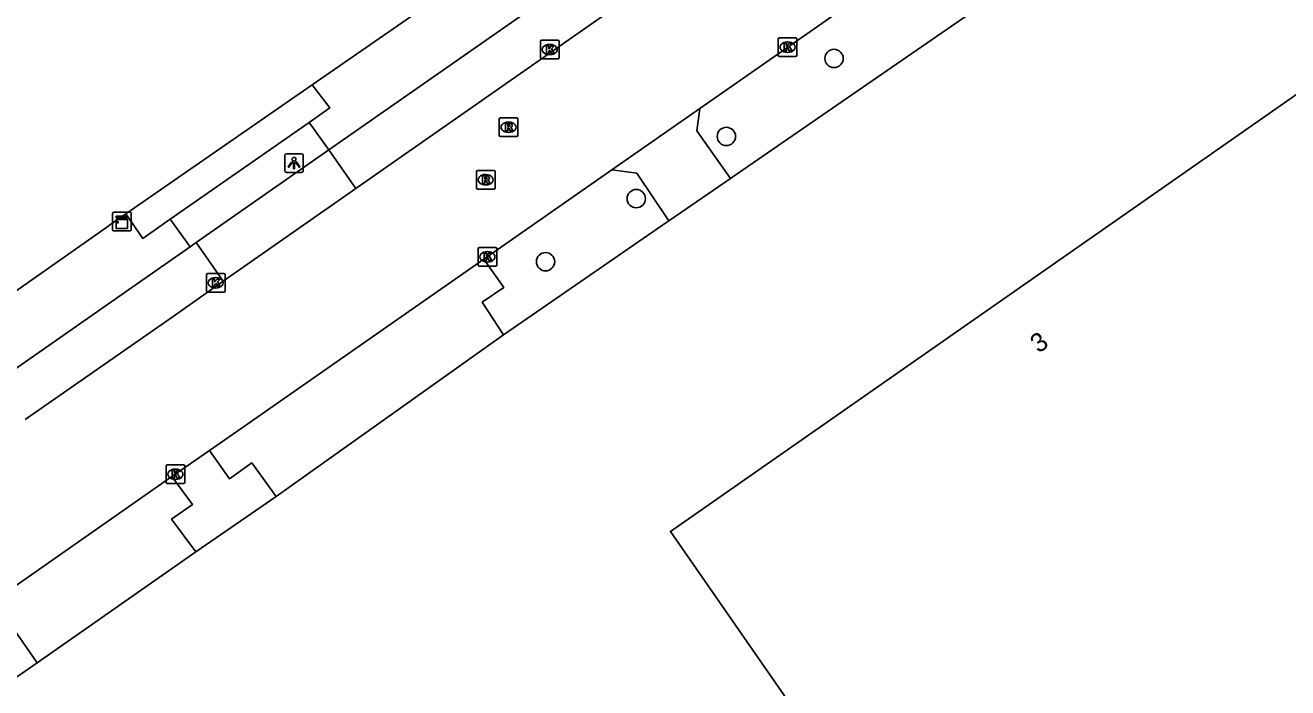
# Model space of a CAD drawing. Extents: x 156651 to 158072, y 387631 to 388990.
# Drawn here: x 157192 to 157259.4, y 388019.3 to 388054.7 of the extents above; entities that cross this region are included whole.
import ezdxf

# ---------------------------------------------------------------- set-up
doc = ezdxf.new("R2010")
doc.units = 0
for name, color, linetype in [('IMGEO_Berm_groen', 7, 'Continuous'), ('IMGEO_Boom', 7, 'Continuous'), ('IMGEO_Groenvoorziening', 7, 'Continuous'), ('IMGEO_Hek', 7, 'Continuous'), ('IMGEO_Kast', 7, 'Continuous'), ('IMGEO_Kolk', 7, 'Continuous'), ('IMGEO_Lichtpunt', 7, 'Continuous'), ('IMGEO_Pand', 7, 'Continuous'), ('IMGEO_Pand_nummerreeks', 7, 'Continuous'), ('IMGEO_Parkeervlak_open', 7, 'Continuous'), ('IMGEO_Rijbaan_lokaal_gesloten', 7, 'Continuous'), ('IMGEO_Rioolput', 7, 'Continuous'), ('IMGEO_Voetpad_open', 7, 'Continuous')]:
    doc.layers.add(name, color=color, linetype=linetype)

msp = doc.modelspace()

# ---------------------------------------------------------------- linework, layer by layer
at = {"layer": 'IMGEO_Berm_groen'}
for points in [[(157229.656, 388046.52), (157229.78, 388046.605), (157243.07, 388055.771)], [(157217.532, 388038.158), (157226.257, 388044.175), (157226.369, 388044.252)], [(157201.094, 388026.55), (157205.385, 388029.517)], [(157173.094, 388007.069), (157192.622, 388020.62)]]:
    msp.add_lwpolyline(points, dxfattribs=at)
at = {"layer": 'IMGEO_Boom'}
for centre in [(157235.188, 388052.93), (157229.437, 388048.762), (157224.623, 388045.438), (157219.777, 388042.063)]:
    msp.add_circle(centre, 0.489, dxfattribs=at)
at = {"layer": 'IMGEO_Groenvoorziening'}
msp.add_lwpolyline([(157207.322, 388051.52), (157197.352, 388044.618)], dxfattribs=at)
at = {"layer": 'IMGEO_Hek'}
for points in [[(157207.322, 388051.52), (157218.564, 388059.333)], [(157197.352, 388044.618), (157207.322, 388051.52)], [(157196.491, 388044.015), (157197.352, 388044.618)], [(157190.094, 388039.531), (157196.391, 388043.945)], [(157196.391, 388043.945), (157196.491, 388044.015)]]:
    msp.add_lwpolyline(points, dxfattribs=at)
at = {"layer": 'IMGEO_Kast'}
for p, q in [((157196.646, 388043.786), (157196.646, 388044.627)), ((157196.646, 388044.627), (157196.646, 388043.786)), ((157196.721, 388044.711), (157197.562, 388044.711)), ((157197.562, 388044.711), (157196.721, 388044.711)), ((157197.646, 388044.636), (157197.646, 388043.795)), ((157197.646, 388043.795), (157197.646, 388044.636)), ((157197.571, 388043.711), (157196.73, 388043.711)), ((157196.73, 388043.711), (157197.571, 388043.711))]:
    msp.add_line(p, q, dxfattribs=at)
for points in [[(157196.841, 388044.501), (157197.441, 388044.501), (157197.441, 388044.416), (157196.841, 388044.416), (157196.841, 388044.501)], [(157196.841, 388044.326), (157197.441, 388044.326), (157197.441, 388043.837), (157196.841, 388043.837), (157196.841, 388044.326)]]:
    msp.add_lwpolyline(points, dxfattribs=at)
msp.add_circle((157196.925, 388044.175), 0.0377, dxfattribs=at)
for centre, start, end in [((157196.724, 388044.633), 92.4484, 184.28452), ((157196.724, 388044.633), 92.4484, 184.28452), ((157197.568, 388044.633), 2.4484, 94.28452), ((157197.568, 388044.633), 2.4484, 94.28452), ((157196.724, 388043.789), 182.4484, 274.28452), ((157196.724, 388043.789), 182.4484, 274.28452), ((157197.568, 388043.789), 272.4484, 4.28452), ((157197.568, 388043.789), 272.4484, 4.28452)]:
    msp.add_arc(centre, 0.0779, start, end, dxfattribs=at)
at = {"layer": 'IMGEO_Kolk'}
for p, q in [((157219.503, 388052.979), (157219.503, 388053.831)), ((157219.578, 388053.905), (157220.43, 388053.905)), ((157220.504, 388053.831), (157220.504, 388052.979)), ((157232.204, 388053.109), (157232.204, 388053.961)), ((157232.279, 388054.035), (157233.131, 388054.035)), ((157232.692, 388053.815), (157232.717, 388053.815)), ((157233.205, 388053.961), (157233.205, 388053.109)), ((157220.014, 388053.125), (157219.989, 388053.125)), ((157219.991, 388053.685), (157220.016, 388053.685)), ((157232.715, 388053.255), (157232.69, 388053.255)), ((157220.43, 388052.905), (157219.578, 388052.905)), ((157233.131, 388053.035), (157232.279, 388053.035)), ((157216.173, 388041.901), (157216.173, 388042.753)), ((157216.248, 388042.827), (157217.1, 388042.827)), ((157216.661, 388042.607), (157216.686, 388042.607)), ((157217.174, 388042.753), (157217.174, 388041.901)), ((157217.1, 388041.827), (157216.248, 388041.827)), ((157216.684, 388042.047), (157216.659, 388042.047)), ((157201.661, 388040.513), (157201.661, 388041.365)), ((157201.736, 388041.439), (157202.588, 388041.439)), ((157202.149, 388041.219), (157202.174, 388041.219)), ((157202.662, 388041.365), (157202.662, 388040.513)), ((157202.588, 388040.439), (157201.736, 388040.439)), ((157202.172, 388040.659), (157202.147, 388040.659)), ((157199.509, 388030.275), (157199.509, 388031.127)), ((157199.584, 388031.201), (157200.436, 388031.201)), ((157199.997, 388030.981), (157200.022, 388030.981)), ((157200.51, 388031.127), (157200.51, 388030.275)), ((157200.436, 388030.201), (157199.584, 388030.201)), ((157200.02, 388030.421), (157199.995, 388030.421))]:
    msp.add_line(p, q, dxfattribs=at)
for points in [[(157219.503, 388052.979), (157219.503, 388053.831)], [(157219.578, 388053.905), (157220.43, 388053.905)], [(157220.504, 388053.831), (157220.504, 388052.979)], [(157232.204, 388053.109), (157232.204, 388053.961)], [(157232.279, 388054.035), (157233.131, 388054.035)], [(157232.525, 388053.735), (157232.648, 388053.735), (157232.648, 388053.584), (157232.778, 388053.735), (157232.942, 388053.735), (157232.796, 388053.584), (157232.949, 388053.335), (157232.797, 388053.335), (157232.712, 388053.499), (157232.648, 388053.432), (157232.648, 388053.335), (157232.525, 388053.335), (157232.525, 388053.735)], [(157233.205, 388053.961), (157233.205, 388053.109)], [(157219.824, 388053.605), (157219.947, 388053.605), (157219.947, 388053.454), (157220.077, 388053.605), (157220.241, 388053.605), (157220.095, 388053.454), (157220.248, 388053.205), (157220.096, 388053.205), (157220.011, 388053.369), (157219.947, 388053.302), (157219.947, 388053.205), (157219.824, 388053.205), (157219.824, 388053.605)], [(157220.43, 388052.905), (157219.578, 388052.905)], [(157233.131, 388053.035), (157232.279, 388053.035)], [(157216.173, 388041.901), (157216.173, 388042.753)], [(157216.248, 388042.827), (157217.1, 388042.827)], [(157216.494, 388042.527), (157216.617, 388042.527), (157216.617, 388042.376), (157216.747, 388042.527), (157216.911, 388042.527), (157216.765, 388042.376), (157216.918, 388042.127), (157216.766, 388042.127), (157216.681, 388042.291), (157216.617, 388042.224), (157216.617, 388042.127), (157216.494, 388042.127), (157216.494, 388042.527)], [(157217.174, 388042.753), (157217.174, 388041.901)], [(157217.1, 388041.827), (157216.248, 388041.827)], [(157201.661, 388040.513), (157201.661, 388041.365)], [(157201.736, 388041.439), (157202.588, 388041.439)], [(157201.982, 388041.139), (157202.105, 388041.139), (157202.105, 388040.988), (157202.235, 388041.139), (157202.399, 388041.139), (157202.253, 388040.988), (157202.406, 388040.739), (157202.254, 388040.739), (157202.169, 388040.903), (157202.105, 388040.836), (157202.105, 388040.739), (157201.982, 388040.739), (157201.982, 388041.139)], [(157202.662, 388041.365), (157202.662, 388040.513)], [(157202.588, 388040.439), (157201.736, 388040.439)], [(157199.509, 388030.275), (157199.509, 388031.127)], [(157199.584, 388031.201), (157200.436, 388031.201)], [(157199.83, 388030.901), (157199.953, 388030.901), (157199.953, 388030.75), (157200.083, 388030.901), (157200.247, 388030.901), (157200.101, 388030.75), (157200.254, 388030.501), (157200.102, 388030.501), (157200.017, 388030.665), (157199.953, 388030.598), (157199.953, 388030.501), (157199.83, 388030.501), (157199.83, 388030.901)], [(157200.51, 388031.127), (157200.51, 388030.275)], [(157200.436, 388030.201), (157199.584, 388030.201)]]:
    msp.add_lwpolyline(points, dxfattribs=at)
for centre, start, end in [((157219.58, 388053.829), 91.55205, 178.44795), ((157219.58, 388053.829), 91.55205, 178.44795), ((157220.428, 388053.829), 1.55205, 88.44795), ((157220.428, 388053.829), 1.55205, 88.44795), ((157232.281, 388053.959), 91.55205, 178.44795), ((157232.281, 388053.959), 91.55205, 178.44795), ((157233.129, 388053.959), 1.55205, 88.44795), ((157233.129, 388053.959), 1.55205, 88.44795), ((157232.281, 388053.111), 181.55205, 268.44795), ((157232.281, 388053.111), 181.55205, 268.44795), ((157233.129, 388053.111), 271.55205, 358.44795), ((157233.129, 388053.111), 271.55205, 358.44795), ((157219.58, 388052.981), 181.55205, 268.44795), ((157219.58, 388052.981), 181.55205, 268.44795), ((157220.428, 388052.981), 271.55205, 358.44795), ((157220.428, 388052.981), 271.55205, 358.44795), ((157216.25, 388042.751), 91.55205, 178.44795), ((157216.25, 388042.751), 91.55205, 178.44795), ((157217.098, 388042.751), 1.55205, 88.44795), ((157217.098, 388042.751), 1.55205, 88.44795), ((157216.25, 388041.903), 181.55205, 268.44795), ((157216.25, 388041.903), 181.55205, 268.44795), ((157217.098, 388041.903), 271.55205, 358.44795), ((157217.098, 388041.903), 271.55205, 358.44795), ((157201.738, 388041.363), 91.55205, 178.44795), ((157201.738, 388041.363), 91.55205, 178.44795), ((157202.586, 388041.363), 1.55205, 88.44795), ((157202.586, 388041.363), 1.55205, 88.44795), ((157201.738, 388040.515), 181.55205, 268.44795), ((157201.738, 388040.515), 181.55205, 268.44795), ((157202.586, 388040.515), 271.55205, 358.44795), ((157202.586, 388040.515), 271.55205, 358.44795), ((157199.586, 388031.125), 91.55205, 178.44795), ((157199.586, 388031.125), 91.55205, 178.44795), ((157200.434, 388031.125), 1.55205, 88.44795), ((157200.434, 388031.125), 1.55205, 88.44795), ((157199.586, 388030.277), 181.55205, 268.44795), ((157199.586, 388030.277), 181.55205, 268.44795), ((157200.434, 388030.277), 271.55205, 358.44795), ((157200.434, 388030.277), 271.55205, 358.44795)]:
    msp.add_arc(centre, 0.0765, start, end, dxfattribs=at)
for centre, major_axis, ratio, start_param, end_param in [((157232.691, 388053.535), (-0.387, 0.002), 0.722429, 4.712389, 7.853982), ((157232.716, 388053.535), (-0.39, 0.002), 0.717154, 1.570796, 4.712389), ((157219.99, 388053.405), (-0.387, 0.002), 0.722429, 4.712389, 7.853982), ((157220.015, 388053.405), (-0.39, 0.002), 0.717154, 1.570796, 4.712389), ((157216.66, 388042.327), (-0.387, 0.002), 0.722429, 4.712389, 7.853982), ((157216.685, 388042.327), (-0.39, 0.002), 0.717154, 1.570796, 4.712389), ((157202.148, 388040.939), (-0.387, 0.002), 0.722429, 4.712389, 7.853982), ((157202.173, 388040.939), (-0.39, 0.002), 0.717154, 1.570796, 4.712389), ((157199.996, 388030.701), (-0.387, 0.002), 0.722429, 4.712389, 7.853982), ((157200.021, 388030.701), (-0.39, 0.002), 0.717154, 1.570796, 4.712389)]:
    msp.add_ellipse(centre, major_axis=major_axis, ratio=ratio, start_param=start_param, end_param=end_param, dxfattribs=at)
at = {"layer": 'IMGEO_Lichtpunt'}
for p, q in [((157205.845, 388047.743), (157205.845, 388046.936)), ((157205.845, 388047.743), (157205.845, 388046.936)), ((157206.747, 388047.838), (157205.939, 388047.838)), ((157206.747, 388047.838), (157205.939, 388047.838)), ((157206.841, 388046.936), (157206.841, 388047.743)), ((157206.841, 388046.936), (157206.841, 388047.743)), ((157205.939, 388046.842), (157206.747, 388046.842)), ((157205.939, 388046.842), (157206.747, 388046.842))]:
    msp.add_line(p, q, dxfattribs=at)
for points in [[(157206.219, 388047.407), (157206.258, 388047.379), (157206.07, 388047.117), (157206.032, 388047.144), (157206.219, 388047.407)], [(157206.321, 388047.359), (157206.368, 388047.359), (157206.368, 388047.037), (157206.321, 388047.037), (157206.321, 388047.359)], [(157206.431, 388047.379), (157206.469, 388047.406), (157206.656, 388047.144), (157206.617, 388047.116), (157206.431, 388047.379)]]:
    msp.add_lwpolyline(points, dxfattribs=at)
msp.add_circle((157206.344, 388047.541), 0.0994, dxfattribs=at)
for centre, start, end in [((157205.939, 388047.743), 90, 180), ((157205.939, 388047.743), 90, 180), ((157206.747, 388047.743), 0, 90), ((157206.747, 388047.743), 0, 90), ((157205.939, 388046.936), 180, 270), ((157205.939, 388046.936), 180, 270), ((157206.747, 388046.936), 270, 0), ((157206.747, 388046.936), 270, 360)]:
    msp.add_arc(centre, 0.0946, start, end, dxfattribs=at)
at = {"layer": 'IMGEO_Pand'}
msp.add_lwpolyline([(157263.242, 388053.365), (157263.091, 388053.246), (157250.631, 388044.541), (157226.45, 388027.647), (157240.973, 388006.687), (157245.602, 388000), (157260.917, 387977.877)], dxfattribs=at)
at = {"layer": 'IMGEO_Parkeervlak_open'}
for points in [[(157229.656, 388046.52), (157227.867, 388049.069), (157228.017, 388050.255)], [(157223.322, 388046.977), (157224.647, 388046.795), (157226.369, 388044.252)], [(157226.369, 388044.252), (157229.656, 388046.52)]]:
    msp.add_lwpolyline(points, dxfattribs=at)
at = {"layer": 'IMGEO_Rijbaan_lokaal_gesloten'}
for points in [[(157228.017, 388050.255), (157240.821, 388059.195)], [(157223.111, 388055.38), (157209.651, 388045.972)], [(157223.322, 388046.977), (157228.017, 388050.255)], [(157216.483, 388042.202), (157223.322, 388046.977)], [(157209.651, 388045.972), (157202.564, 388041.019)], [(157201.832, 388031.98), (157203.874, 388033.405), (157216.483, 388042.202)], [(157202.564, 388041.019), (157199.881, 388039.143), (157191.985, 388033.624)], [(157199.818, 388030.58), (157201.832, 388031.98)], [(157189.11, 388023.09), (157199.818, 388030.58)]]:
    msp.add_lwpolyline(points, dxfattribs=at)
at = {"layer": 'IMGEO_Rioolput'}
for p, q in [((157217.303, 388048.827), (157217.303, 388049.679)), ((157217.378, 388049.753), (157218.23, 388049.753)), ((157218.304, 388049.679), (157218.304, 388048.827)), ((157217.791, 388049.533), (157217.816, 388049.533)), ((157218.23, 388048.753), (157217.378, 388048.753)), ((157217.814, 388048.973), (157217.789, 388048.973)), ((157216.082, 388046.022), (157216.082, 388046.874)), ((157216.157, 388046.948), (157217.009, 388046.948)), ((157216.57, 388046.728), (157216.595, 388046.728)), ((157217.083, 388046.874), (157217.083, 388046.022)), ((157217.009, 388045.948), (157216.157, 388045.948)), ((157216.593, 388046.168), (157216.568, 388046.168))]:
    msp.add_line(p, q, dxfattribs=at)
for points in [[(157217.303, 388048.827), (157217.303, 388049.679)], [(157217.378, 388049.753), (157218.23, 388049.753)], [(157218.304, 388049.679), (157218.304, 388048.827)], [(157217.892, 388049.451), (157217.64, 388049.453), (157217.64, 388049.053)], [(157217.64, 388049.053), (157217.764, 388049.053), (157217.764, 388049.215), (157217.775, 388049.215)], [(157217.818, 388049.372), (157217.764, 388049.372), (157217.764, 388049.291)], [(157217.764, 388049.291), (157217.816, 388049.291)], [(157217.822, 388049.186), (157217.893, 388049.053), (157218.033, 388049.053), (157217.968, 388049.179)], [(157218.23, 388048.753), (157217.378, 388048.753)], [(157216.082, 388046.022), (157216.082, 388046.874)], [(157216.157, 388046.948), (157217.009, 388046.948)], [(157216.671, 388046.646), (157216.419, 388046.648), (157216.419, 388046.248)], [(157216.419, 388046.248), (157216.543, 388046.248), (157216.543, 388046.41), (157216.554, 388046.41)], [(157216.597, 388046.567), (157216.543, 388046.567), (157216.543, 388046.486)], [(157216.543, 388046.486), (157216.595, 388046.486)], [(157216.601, 388046.381), (157216.672, 388046.248), (157216.812, 388046.248), (157216.747, 388046.374)], [(157217.083, 388046.874), (157217.083, 388046.022)], [(157217.009, 388045.948), (157216.157, 388045.948)]]:
    msp.add_lwpolyline(points, dxfattribs=at)
for centre, radius, start, end in [((157217.38, 388049.677), 0.0765, 91.55205, 178.44795), ((157217.38, 388049.677), 0.0765, 91.55205, 178.44795), ((157218.228, 388049.677), 0.0765, 1.55205, 88.44795), ((157218.228, 388049.677), 0.0765, 1.55205, 88.44795), ((157217.774, 388049.162), 0.0533, 26.02933, 88.69889), ((157217.8, 388049.48), 0.19, 274.7715, 282.96867), ((157217.824, 388049.276), 0.0964, 77.00612, 93.18647), ((157217.838, 388049.333), 0.0378, 276.66336, 79.67722), ((157217.891, 388049.341), 0.109, 350.36119, 89.41601), ((157217.889, 388049.341), 0.112, 277.58423, 350.98172), ((157217.873, 388049.126), 0.108, 29.51342, 73.79051), ((157217.38, 388048.829), 0.0765, 181.55205, 268.44795), ((157217.38, 388048.829), 0.0765, 181.55205, 268.44795), ((157218.228, 388048.829), 0.0765, 271.55205, 358.44795), ((157218.228, 388048.829), 0.0765, 271.55205, 358.44795), ((157216.159, 388046.872), 0.0765, 91.55205, 178.44795), ((157216.159, 388046.872), 0.0765, 91.55205, 178.44795), ((157216.553, 388046.357), 0.0533, 26.02933, 88.69889), ((157216.579, 388046.675), 0.19, 274.7715, 282.96867), ((157216.603, 388046.471), 0.0964, 77.00612, 93.18647), ((157216.617, 388046.528), 0.0378, 276.66336, 79.67722), ((157216.67, 388046.536), 0.109, 350.36119, 89.41601), ((157216.668, 388046.536), 0.112, 277.58423, 350.98172), ((157216.652, 388046.321), 0.108, 29.51342, 73.79051), ((157217.007, 388046.872), 0.0765, 1.55205, 88.44795), ((157217.007, 388046.872), 0.0765, 1.55205, 88.44795), ((157216.159, 388046.024), 0.0765, 181.55205, 268.44795), ((157216.159, 388046.024), 0.0765, 181.55205, 268.44795), ((157217.007, 388046.024), 0.0765, 271.55205, 358.44795), ((157217.007, 388046.024), 0.0765, 271.55205, 358.44795)]:
    msp.add_arc(centre, radius, start, end, dxfattribs=at)
for centre, major_axis, ratio, start_param, end_param in [((157217.79, 388049.253), (-0.387, 0.002), 0.722429, 4.712389, 7.853982), ((157217.815, 388049.253), (-0.39, 0.002), 0.717154, 1.570796, 4.712389), ((157216.569, 388046.448), (-0.387, 0.002), 0.722429, 4.712389, 7.853982), ((157216.594, 388046.448), (-0.39, 0.002), 0.717154, 1.570796, 4.712389)]:
    msp.add_ellipse(centre, major_axis=major_axis, ratio=ratio, start_param=start_param, end_param=end_param, dxfattribs=at)
at = {"layer": 'IMGEO_Voetpad_open'}
for points in [[(157218.564, 388059.333), (157207.322, 388051.52)], [(157221.662, 388057.453), (157208.195, 388048.04)], [(157207.159, 388049.511), (157208.253, 388050.284), (157207.322, 388051.52)], [(157207.159, 388049.511), (157199.726, 388044.331)], [(157208.195, 388048.04), (157207.159, 388049.511)], [(157208.195, 388048.04), (157201.12, 388043.085)], [(157209.651, 388045.972), (157208.195, 388048.04)], [(157197.352, 388044.618), (157196.491, 388044.015), (157196.391, 388043.945), (157190.094, 388039.531)], [(157197.352, 388044.618), (157198.27, 388043.303), (157199.726, 388044.331)], [(157199.726, 388044.331), (157200.801, 388042.861)], [(157200.801, 388042.861), (157201.12, 388043.085)], [(157201.12, 388043.085), (157202.564, 388041.019)], [(157200.801, 388042.861), (157198.442, 388041.212), (157190.647, 388035.765)], [(157217.532, 388038.158), (157216.399, 388039.902), (157217.546, 388040.691), (157216.483, 388042.202)], [(157205.385, 388029.517), (157206.185, 388030.086), (157217.532, 388038.158)], [(157201.832, 388031.98), (157202.892, 388030.458), (157204.087, 388031.312), (157205.385, 388029.517)], [(157201.094, 388026.55), (157199.801, 388028.306), (157200.914, 388029.083), (157199.818, 388030.58)], [(157192.622, 388020.62), (157201.094, 388026.55)], [(157189.11, 388023.09), (157190.184, 388021.576), (157191.37, 388022.424), (157192.622, 388020.62)]]:
    msp.add_lwpolyline(points, dxfattribs=at)

# ---------------------------------------------------------------- texts
at = {"layer": 'IMGEO_Pand_nummerreeks'}
msp.add_text('3', height=1, rotation=34.729, dxfattribs=at).set_placement((157246.111, 388037.143))

doc.saveas('drawing.dxf')
